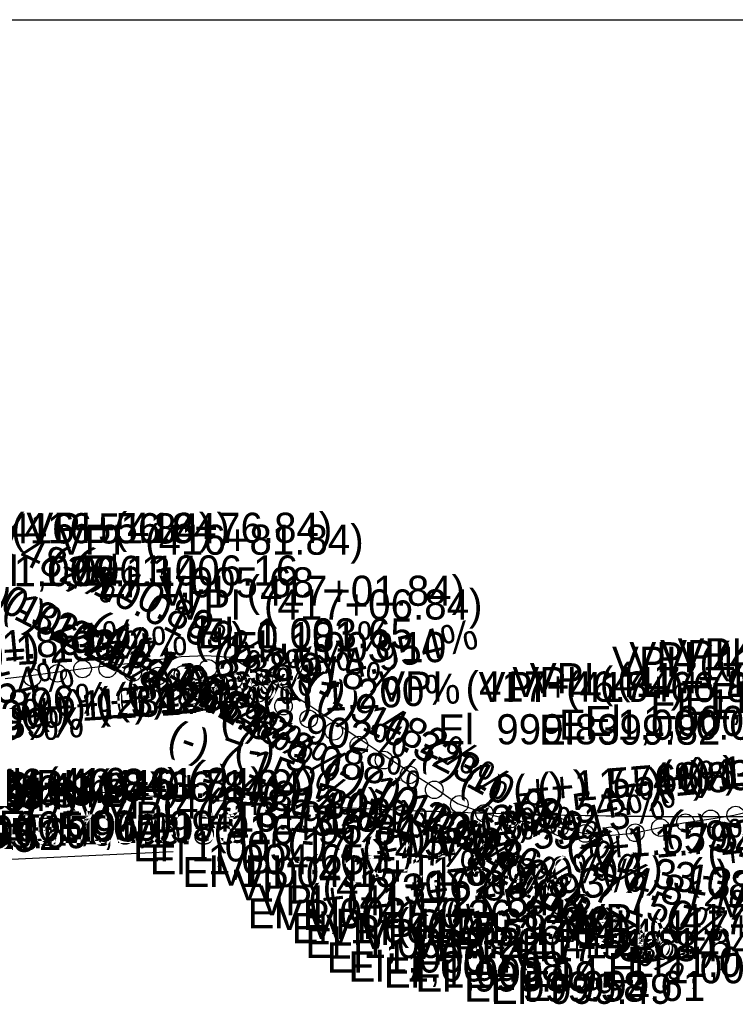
# Model space of a CAD drawing. Extents: x 150 to 16976893, y 3102 to 12559827.
# Drawn here: x 16976032.2 to 16976174.7, y 12558903.2 to 12559099.3 of the extents above; entities that cross this region are included whole.
import ezdxf

# ---------------------------------------------------------------- set-up
doc = ezdxf.new("R2010")
doc.units = 0
for name, color, linetype in [('RD_DDB_GradeTX', 7, 'Continuous'), ('RD_DDB_PI', 7, 'Continuous'), ('RD_DDB_Profile_EX', 7, 'Continuous'), ('RD_HC_TX_Sta20', 7, 'Continuous'), ('RD_XS_Misc_Line', 7, 'Continuous')]:
    doc.layers.add(name, color=color, linetype=linetype)

msp = doc.modelspace()

# ---------------------------------------------------------------- linework, layer by layer
at = {"layer": 'RD_DDB_PI'}
msp.add_line((16976062.8, 12558933.55), (16975974.65, 12558929.35), dxfattribs=at)
for centre in [(16976044.74, 12558969.96), (16976049.74, 12558970.01), (16976069.74, 12558970.09), (16976034.74, 12558968.28), (16976039.74, 12558969.11), (16976054.74, 12558969.28), (16976059.74, 12558968.55), (16976064.74, 12558968.85), (16976074.74, 12558967.72), (16976079.74, 12558965.14), (16976084.74, 12558962.58), (16976089.74, 12558960.05), (16976094.74, 12558957.55), (16976099.74, 12558954.82), (16976104.74, 12558951.83), (16976109.74, 12558948.87), (16976114.74, 12558945.91), (16976119.74, 12558943.01), (16976124.74, 12558941.23), (16976129.74, 12558940.02), (16976169.74, 12558940.13), (16976174.74, 12558940.88), (16976134.74, 12558939.24), (16976139.74, 12558938.47), (16976159.74, 12558938.39), (16976164.74, 12558939.37), (16976144.74, 12558937.22), (16976149.74, 12558936.78), (16976154.74, 12558937.36)]:
    msp.add_circle(centre, 1.75, dxfattribs=at)
at = {"layer": 'RD_DDB_Profile_EX'}
msp.add_lwpolyline([(16976029.37, 12558968.05), (16976034.37, 12558968.67), (16976039.37, 12558969.33), (16976044.37, 12558970), (16976049.37, 12558970.6), (16976054.37, 12558971.13), (16976059.37, 12558971.81), (16976064.37, 12558972.48), (16976069.37, 12558972.68), (16976074.37, 12558972.29), (16976079.37, 12558969.2), (16976084.37, 12558966.15), (16976089.37, 12558963.12), (16976094.37, 12558959.77), (16976099.37, 12558956.4), (16976104.37, 12558953.07), (16976109.37, 12558949.82), (16976114.37, 12558946.64), (16976119.37, 12558943.16), (16976124.37, 12558941.37), (16976129.37, 12558940.09), (16976134.37, 12558939.3), (16976139.37, 12558938.53), (16976144.37, 12558937.29), (16976149.37, 12558936.82), (16976154.37, 12558937.29), (16976159.37, 12558938.33), (16976164.37, 12558939.33), (16976169.37, 12558940.09), (16976174.37, 12558940.84), (16976179.37, 12558942.07)], dxfattribs=at)
at = {"layer": 'RD_HC_TX_Sta20'}
msp.add_line((16975697.9, 12559099.27), (16976247.9, 12559099.27), dxfattribs=at)
at = {"layer": 'RD_XS_Misc_Line'}
msp.add_spline([(16975697.9, 12559011.77), (16975708.9, 12559008.5), (16975719.9, 12559005.32), (16975730.9, 12559002.21), (16975741.9, 12558999.18), (16975752.9, 12558996.22), (16975763.9, 12558993.34), (16975774.9, 12558990.54), (16975785.9, 12558987.81), (16975796.9, 12558985.16), (16975807.9, 12558982.59), (16975818.9, 12558980.09), (16975829.9, 12558977.67), (16975840.9, 12558975.33), (16975851.9, 12558973.06), (16975862.9, 12558970.87), (16975873.9, 12558968.76), (16975884.9, 12558966.72), (16975895.9, 12558964.76), (16975906.9, 12558962.87), (16975917.9, 12558961.06), (16975928.9, 12558959.33), (16975939.9, 12558957.67), (16975950.9, 12558956.09), (16975961.9, 12558954.59), (16975972.9, 12558953.17), (16975983.9, 12558951.82), (16975994.9, 12558950.54), (16976005.9, 12558949.35), (16976016.9, 12558948.23), (16976027.9, 12558947.18), (16976038.9, 12558946.21), (16976049.9, 12558945.32), (16976060.9, 12558944.51), (16976071.9, 12558943.77), (16976082.9, 12558943.11), (16976093.9, 12558942.52), (16976104.9, 12558942.02), (16976115.9, 12558941.58), (16976126.9, 12558941.23), (16976137.9, 12558940.95), (16976148.9, 12558940.75), (16976159.9, 12558940.62), (16976170.9, 12558940.57), (16976181.9, 12558940.6), (16976192.9, 12558940.7), (16976203.9, 12558940.88), (16976214.9, 12558941.14), (16976225.9, 12558941.47), (16976236.9, 12558941.88), (16976247.9, 12558942.36)], degree=3, dxfattribs=at)

# ---------------------------------------------------------------- texts
at = {"layer": 'RD_DDB_GradeTX'}
for s, rotation, p in [('(-) 9.482%', 334.6339, (16976016.39, 12558998.71)), ('(-) 10.323%', 332.6985, (16976014.92, 12558988.47)), ('(-) 10.016%', 333.3987, (16976037.33, 12558989.66)), ('(-) 10.899%', 331.4123, (16976042.13, 12558989.64)), ('(-) 10.221%', 332.9308, (16976021.61, 12558984.74)), ('(-) 10.118%', 333.1642, (16976028.42, 12558980.99)), ('(-) 11.971%', 329.0974, (16976045.41, 12558976.86)), ('(+) 1.861%', 5.3174, (16976016.79, 12558970.38)), ('(-) 11.864%', 329.3244, (16976048.74, 12558974.59)), ('(+) 0.181%', 0.5182, (16976067.02, 12558973.16)), ('(+) 4.954%', 13.9119, (16976085.57, 12558964.74)), ('(+) 1.233%', 3.5276, (16976019.34, 12558969.99)), ('(+) 1.212%', 3.4666, (16976026.35, 12558970.4)), ('(-) 11.838%', 329.3795, (16976053.26, 12558971.84)), ('(+) 3.386%', 9.6093, (16976059.51, 12558963.33)), ('(-) 2.918%', 351.7001, (16976070.49, 12558970.01)), ('(+) 3.332%', 9.4599, (16976053.85, 12558962.34)), ('(+) 4.954%', 13.9119, (16976005.18, 12558957.19)), ('(-) 11.578%', 329.934, (16976058.42, 12558968.11)), ('(+) 1.998%', 5.7045, (16976051.42, 12558960.9)), ('(-) 9.482%', 334.6339, (16976088.19, 12558964.66)), ('(+) 1.896%', 5.4144, (16976011.38, 12558957.85)), ('(+) 1.342%', 3.8385, (16976035.53, 12558959.09)), ('(+) 1.420%', 4.0611, (16976040.86, 12558959.52)), ('(+) 1.519%', 4.3438, (16976047.66, 12558960.12)), ('(+) 1.200%', 3.4329, (16976080.66, 12558960.79)), ('(-) 10.323%', 332.6985, (16976090.95, 12558962.73)), ('(+) 1.281%', 3.6644, (16976032.34, 12558958.82)), ('(+) 1.200%', 3.4329, (16976000.81, 12558956)), ('(-) 2.902%', 351.7438, (16976071.9, 12558957.69)), ('(+) 0.019%', 0.0545, (16976000.52, 12558955.81)), ('(+) 0.189%', 0.5407, (16976005.59, 12558955.99)), ('(-) 7.150%', 340.3289, (16976061.28, 12558954.35)), ('(-) 3.088%', 351.2241, (16976074.68, 12558951.55)), ('(-) 10.899%', 331.4123, (16976111.77, 12558951.69)), ('(+) 1.611%', 4.6059, (16976158.77, 12558944.9)), ('(+) 1.432%', 4.0959, (16976159.93, 12558945.52)), ('(+) 1.398%', 3.9989, (16976165.16, 12558946)), ('(-) 4.814%', 346.467, (16976065.3, 12558946.27)), ('(-) 10.221%', 332.9308, (16976092.3, 12558948.61)), ('(+) 1.574%', 4.4998, (16976130.65, 12558942.67)), ('(+) 1.566%', 4.4779, (16976135.47, 12558943.08)), ('(+) 1.837%', 5.2476, (16976150.39, 12558943.5)), ('(-) 5.001%', 345.9615, (16976080.02, 12558944.12)), ('(-) 10.118%', 333.1642, (16976099.26, 12558945.15)), ('(-) 11.971%', 329.0974, (16976119.51, 12558946.49)), ('(-) 10.016%', 333.3987, (16976102.96, 12558943.37)), ('(+) 3.547%', 10.0575, (16976124.23, 12558935.74)), ('(-) 3.133%', 351.0961, (16976068.9, 12558940.44)), ('(+) 5.113%', 14.3396, (16976122.85, 12558930.7)), ('(+) 3.025%', 8.6021, (16976103.39, 12558933.13)), ('(+) 4.146%', 11.7127, (16976096.47, 12558928.34)), ('(+) 3.916%', 11.0782, (16976100.96, 12558929.94)), ('(-) 5.001%', 345.9615, (16976160.39, 12558936.4)), ('(+) 1.559%', 4.4561, (16976141.17, 12558931.51)), ('(+) 1.792%', 5.1194, (16976146.63, 12558931.25)), ('(+) 2.307%', 6.5804, (16976169.41, 12558929.99)), ('(-) 1.744%', 355.0162, (16976085.38, 12558933.36)), ('(-) 11.864%', 329.3244, (16976116.84, 12558934.19)), ('(-) 11.838%', 329.3795, (16976121.4, 12558931.51)), ('(-) 3.133%', 351.0961, (16976147.87, 12558928.07)), ('(+) 2.990%', 8.5027, (16976110.79, 12558922.22)), ('(+) 5.093%', 14.2874, (16976117.71, 12558917.07)), ('(-) 11.578%', 329.934, (16976126.98, 12558928.42)), ('(-) 7.150%', 340.3289, (16976136.32, 12558927.53)), ('(-) 4.814%', 346.467, (16976142.94, 12558927.59)), ('(-) 3.088%', 351.2241, (16976151.85, 12558927.49)), ('(-) 1.744%', 355.0162, (16976165.06, 12558926.41)), ('(+) 2.307%', 6.5804, (16976089.97, 12558920.83))]:
    msp.add_text(s, height=6, rotation=rotation, dxfattribs=at).set_placement(p)
at = {"layer": 'RD_DDB_PI'}
for s, p in [('VPI  (416+51.84)', (16976009.69, 12558994.96)), ('VPI  (416+56.84)', (16976013.16, 12558995.01)), ('VPI  (416+76.84)', (16976033.57, 12558995.09)), ('VPI  (416+81.84)', (16976039.81, 12558992.72)), ('El  1,006.13', (16976019.44, 12558986.46)), ('El  1,006.14', (16976024.82, 12558986.51)), ('El  1,006.16', (16976044.82, 12558986.59)), ('El  1,005.68', (16976047.96, 12558984.22)), ('VPI  (417+01.84)', (16976059.99, 12558982.55)), ('VPI  (417+06.84)', (16976063.45, 12558979.82)), ('El  1,003.65', (16976067.66, 12558974.05)), ('El  1,003.10', (16976074.29, 12558971.32)), ('VPI  (417+96.84)', (16976153.57, 12558969.31)), ('VPI  (418+01.84)', (16976159.69, 12558969.71)), ('VPI  (418+06.84)', (16976163.16, 12558970.1)), ('VPI  (417+91.84)', (16976150.11, 12558968.43)), ('VPI  (417+76.84)', (16976133.75, 12558965.13)), ('VPI  (417+46.84)', (16976103.57, 12558963.47)), ('VPI  (417+66.84)', (16976123.57, 12558963.39)), ('VPI  (417+71.84)', (16976130.28, 12558964.37)), ('El  1,001.08', (16976169.61, 12558961.21)), ('El  1,000.82', (16976157.72, 12558959.93)), ('El  1,001.00', (16976164.58, 12558960.81)), ('El  1,000.01', (16976139.58, 12558955.87)), ('El  1,000.16', (16976144.7, 12558956.63)), ('El  999.83', (16976115.5, 12558954.97)), ('El  999.82', (16976135.56, 12558954.89)), ('VPI  (416+46.84)', (16976003.39, 12558944.11)), ('VPI  (416+61.84)', (16976019.93, 12558944.28)), ('VPI  (416+66.84)', (16976023.39, 12558943.55)), ('VPI  (416+71.84)', (16976030.11, 12558943.85)), ('VPI  (416+16.84)', (16975974.93, 12558941.39)), ('VPI  (416+21.84)', (16975979.57, 12558941.71)), ('VPI  (416+26.84)', (16975983.04, 12558942.05)), ('VPI  (416+31.84)', (16975989.51, 12558942.4)), ('VPI  (416+36.84)', (16975992.98, 12558942.78)), ('VPI  (416+41.84)', (16975999.93, 12558943.28)), ('VPI  (416+86.84)', (16976043.27, 12558940.14)), ('VPI  (416+91.84)', (16976049.93, 12558937.58)), ('El  1,005.96', (16976013.05, 12558935.61)), ('El  1,005.99', (16976028.05, 12558935.78)), ('El  1,005.55', (16975992.61, 12558933.55)), ('El  1,005.62', (16975997.72, 12558933.9)), ('El  1,005.69', (16976003.05, 12558934.28)), ('El  1,005.79', (16976008.23, 12558934.78)), ('El  1,005.85', (16976032.72, 12558935.05)), ('El  1,005.91', (16976039.58, 12558935.35)), ('VPI  (416+96.84)', (16976053.39, 12558935.05)), ('El  1,005.17', (16976054.76, 12558931.64)), ('El  1,004.65', (16976058.08, 12558929.08)), ('El  1,004.15', (16976064.61, 12558926.55)), ('VPI  (417+11.84)', (16976071.64, 12558926.83)), ('VPI  (417+16.84)', (16976075.11, 12558923.87)), ('VPI  (417+21.84)', (16976079.75, 12558920.91)), ('VPI  (418+11.84)', (16976171.35, 12558920.49)), ('El  1,002.50', (16976077.58, 12558918.33)), ('VPI  (417+26.84)', (16976083.22, 12558918.01)), ('VPI  (417+31.84)', (16976089.69, 12558916.23)), ('VPI  (417+81.84)', (16976139.99, 12558915.88)), ('VPI  (417+86.84)', (16976143.45, 12558917.15)), ('El  1,001.91', (16976086.36, 12558915.37)), ('VPI  (417+36.84)', (16976093.16, 12558915.02)), ('VPI  (417+41.84)', (16976100.11, 12558914.24)), ('El  1,001.32', (16976089.08, 12558912.41)), ('VPI  (417+51.84)', (16976109.87, 12558912.22)), ('VPI  (417+61.84)', (16976120.11, 12558912.36)), ('VPI  (417+56.84)', (16976113.33, 12558911.78)), ('El  1,000.74', (16976093.34, 12558909.51)), ('El  1,000.57', (16976153.11, 12558908.65)), ('El  1,000.38', (16976097.66, 12558907.73)), ('El  1,000.14', (16976104.7, 12558906.52)), ('El  1,000.31', (16976149.29, 12558907.38)), ('El  999.99', (16976111, 12558905.74)), ('El  999.58', (16976120.68, 12558903.72)), ('El  999.49', (16976126, 12558903.28)), ('El  999.61', (16976132.54, 12558903.86))]:
    msp.add_text(s, height=6, dxfattribs=at).set_placement(p)

doc.saveas('drawing.dxf')
